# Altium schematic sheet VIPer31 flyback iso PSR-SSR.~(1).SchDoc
size A3; PageSetup: Record=PageOptions¦CenterHorizontal=True¦CenterVertical=True¦PrintScale=0.73¦XCorrection=1.00¦YCorrection=1.00¦PrintKind=1¦BorderSize=5000000¦LeftOffset=0¦BottomOffset=0¦Orientation=2¦PaperLength=1000¦PaperWidth=1000¦Scale=100¦PaperSource=7¦PrintQuality=-3¦MediaType=1¦DitherType=10¦PrintScaleMode=1¦PaperKind=A4¦PaperIndex=9
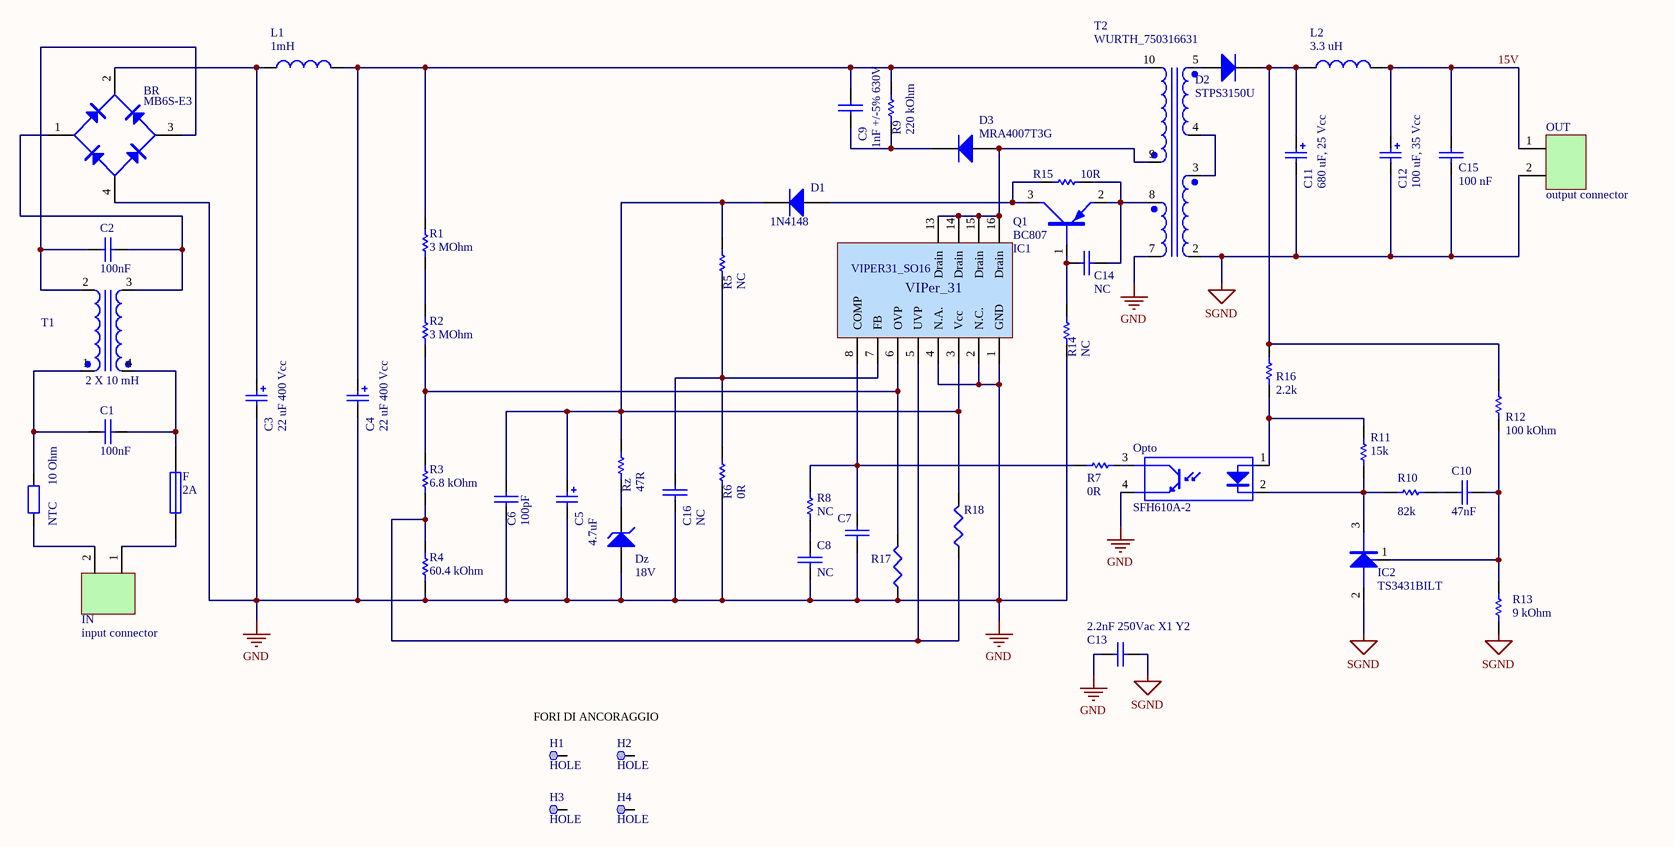
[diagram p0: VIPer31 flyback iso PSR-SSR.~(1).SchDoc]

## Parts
BR  MB6S-E3  [BRIDGE]
C1  100nF  [CAP-13X6]
C2  100nF  [CAP-13X6]
C3  22 uF 400 Vcc  [CAPOL-7.5X16]
C4  22 uF 400 Vcc  [CAPOL-7.5X16]
C5  4.7uF  [R-1206-B2]
C6  100pF  [R-0603-B2]
C7  1 nF 200 Vdc  [R-0603-B2]  (value not drawn)
C8  NC  [R-0603-B2]
C9  1nF +/-5% 630V  [R-1206-B2]
C10  47nF  [R-0603-B2]
C11  680 uF, 25 Vcc  [CAPOL-5X10]
C12  100 uF, 35 Vcc  [CAPOL-2.5X6.3]
C13  2.2nF 250Vac X1 Y2  [MYLAR-10X6]
C14  NC  [R-0603-B2]
C15  100 nF  [R-0603-B2]
C16  NC  [R-0603-B2]
D1  1N4148  [SOD-123]
D2  STPS3150U  [SMB-2]
D3  MRA4007T3G  [SMA-2]
Dz  18V  [SOD-123]
F  2A  [Fuse_3821200041_Wick]
H1  HOLE  [FORO]
H2  HOLE  [FORO]
H3  HOLE  [FORO]
H4  HOLE  [FORO]
IC1  VIPER31_SO16  [SO-16N_2]
IC2  TS3431BILT  [SOT23-3-MIRR]
IN  input connector  [SM.2VITE]
L1  1mH  [CAPOL-5X10]
L2  3.3 uH  [WE_74404043033A_4x4]
NTC  10 Ohm  [B57237S100M-NTC]
Opto  SFH610A-2  [DIP4]
OUT  output connector  [SM.2VITE]
Q1  BC807  [BC817_NEW]
R1  3 MOhm  [R-0805-B2]
R2  3 MOhm  [R-0805-B2]
R3  6.8 kOhm  [R-0805-B2]
R4  60.4 kOhm  [R-0805-B2]
R5  NC  [R-0603-B2]
R6  0R  [R-0603-B2]
R7  0R  [RES-1/4W-3]
R8  NC  [R-0603-B2]
R9  220 kOhm  [R-1206-B2]
R10  82k  [R-0603-B2]
R11  15k  [R-0603-B2]
R12  100 kOhm  [R-0603-B2]
R13  9 kOhm  [R-0603-B2]
R14  NC  [R-0603-B2]
R15  10R  [R-0805-B]
R16  2.2k  [R-0603-B2]
R17  RESISTENZA  [R-0603-B2]  (value not drawn)
R18  RESISTENZA  [R-0603-B2]  (value not drawn)
Rz  47R  [R-0603-B2]
T1  2 X 10 mH  [WE_744821110_Choke]
T2  WURTH_750316631  [WURTH_750316631]

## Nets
GND: BR.4(V-) C3.2 C4.2 C5.2 C6.2 C7.2 C8.2 C13.2 C16.2 Dz.1(A) IC1.1(GND) IC1.2(N.C.) IC1.4(N.A.) Opto.4(E) R4.1 R6.1 R14.1 R17.1 T2.7(OUT)
SGND: C11.2 C12.2 C13.1 C15.2 IC2.2(A) OUT.2 R13.1 T2.2(HV)
15V: C12.1 C15.1 L2.2 OUT.1
NetBR_1: BR.1(AC) C2.2 T1.3(PC)
NetBR_2: BR.2(V+) C3.1 L1.1
NetBR_3: BR.3(AC) C2.1 T1.2(GND)
NetC1_1: C1.1 NTC.2 T1.1(SLS)
NetC1_2: C1.2 F.2 T1.4(LAMP)
NetC4_1: C4.1 C9.1 L1.2 R1.2 R9.2 T2.10(S_GND)
NetC5_1: C5.1 C6.1 D1.2(K) IC1.3(Vcc) R5.2 R18.2 Rz.2
NetC7_1: C7.1 IC1.8(COMP) R7.2 R8.2
NetC8_1: C8.1 R8.1
NetC9_2: C9.2 D3.2(K) R9.1
NetC10_1: C10.1 IC2.1(Ref) R12.1 R13.2
NetC10_2: C10.2 R10.1
NetC11_1: C11.1 D2.2(K) L2.1 R12.2 R16.2
NetC14_1: C14.1 Q1.1(B) R14.2
NetC14_2: C14.2 Q1.2(E) R15.1 T2.8(OUT)
NetC16_1: C16.1 IC1.7(FB) R5.1 R6.2
NetD1_1: D1.1(A) Q1.3(C) R15.2
NetD2_1: D2.1(A) T2.5(P_GND)
NetD3_1: D3.1(A) IC1.13(Drain) IC1.14(Drain) IC1.15(Drain) IC1.16(Drain) T2.9(OUT)
NetDz_2: Dz.2(K) Rz.1
NetF_1: F.1 IN.1
NetIC1_5: IC1.5(UVP) R3.1 R4.2 R18.1
NetIC1_6: IC1.6(OVP) R2.1 R3.2 R17.2
NetIC2_3: IC2.3(K) Opto.2(K) R10.2 R11.1
NetIN_2: IN.2 NTC.1
NetOpto_1: Opto.1(A) R11.2 R16.1
NetOpto_3: Opto.3(C) R7.1
NetR1_1: R1.1 R2.2
NetT2_3: T2.3(DR.) T2.4(VDD)

Not connected (* = marked no-connect by the designer): H1 1; H2 1; H3 1; H4 1

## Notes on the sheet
- FORI DI ANCORAGGIO

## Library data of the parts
BR = BRIDGE1: Diode Bridge
C1 C2 C6 = CAP: 100 pF 250 Vdc multi layer capacitor; Part number: CGA3E3C0G2E101J080AA; Value: 100 pF +/-5%, 250 Vdc
C3 C4 = Cap Pol1: Polarized Capacitor (Radial); Part number: 400BXC68MEFC18X25; Value: 68 uF +/-20%, 400 Vcc, +105°C
C5 = Cap Pol1: Vcc cap 4.7uF 50 Vcc, Kemet; Part number: 35ML10MEFC4X7; Value: 10uF +/-20%, 35 Vcc, +105°C
C7 = CAP: 1 nF 200 Vdc multi layer capacitor; Part number: C0603C102J2GACAUTO; Value: 1 nF +/-5%, 200 Vdc
C8 C14 C16 = CAP
C9 = CAP: 1 nF 630 V multi layer capacitor; Part number: C3216C0G2J102J085AA; Value: 1 nF 630 Vdc
C10 = CAP: 22 nF +/-10%, 100 Vcc, MLCC; Part number: GCM188R72A223KA37D; Value: 22nF, ±10%, 100Vcc
C11 = Cap Pol1: 470 uF +/-20%, 35 Vcc, +105°C; Part number: 25ZLH470MEFC10X12.5
C12 = Cap Pol1: 100 uF +/-20%, 35 Vcc, +105°C; Part number: 35ZLH100MEFC6.3X11
C13 = CAP: 2.2 nF 2000 V single layer capacitor; Part number: DE2E3KY222MA2BM01F
C15 = CAP: 100nF ±10%, 25 Vcc, MLCC; Part number: C0603C104K3RACTU
D1 = Diode: small signal diode; Part number: STPS1150A; Value: 1 A, 150 V
D2 = Diode: Schottky diode, 10A, 200 V; Part number: STPS2200UF
D3 = Diode: Silicon Diode, 1 A, 1000 V
Dz = D Zener: Zener Diode; Part number: MMSZ5248B-V-GS08; Value: 18W, 500 mW
F = Fuse 1: Fuse 2A,  250 Vca; Part number: 3403.0169.24
IC1 = VIPER31_SO16: Integrato
IC2 = TS432: 1.24 V VREF SHUNT; Part number: TS432ILT
IN OUT = M.2VITE: Morsetti
L1 L2 = Inductor: FIXED IND 3.3UH 3.23A 33 MOHM; Part number: 74404043033A
NTC = Res2: Part number: NTPA7100LBMB0
Opto = OPTO_1: Opto ingresso 60 Vdc
Q1 = PNP_BC807: PNP Transitstor 0.5A, 45 V, hfe 30; Part number: BC807-40LT3G
R1 R2 = Res1: 3 MOhm +/-1%  0.125W, 0805 Vishay; Part number: ERJP08J105V; Value: 1MOhm +/-5%
R3 = Res1: 6.8 kOhm +/-1% 0.125W, 0805 Panasonic; Part number: ERJP08J105V; Value: 1MOhm +/-5%
R4 = Res1: 60.4 kOhm +/-1% 0.125W, 0805 Panasonic; Part number: ERJP08J105V; Value: 1MOhm +/-5%
R5 R8 R14 = Res1: Not connected
R6 R7 = Res1: 0Ω, 0.25W, pkg 0603, serie CRCW; Part number: CRCW06030000Z0EAHP; Value: 0 Ohm, 0.25W
R9 = Res1: 220 KOhm +/-5%, 0.33W, 1206, serie ERJT08; Part number: ERJT08J224V
R10 = Res1: 470kΩ ±1%, 0.1W; Part number: CRCW0603470KFKEA
R11 = Res1: 22KΩ ±1%, 0.1W; Part number: CRCW060322K0FKEA
R12 = Res1: Not connected; Part number: CRCW0603130KFKEA; Value: 130 kΩ ±1%, 0.1 W
R13 = Res1: 15 kΩ ±1%, 0.1W, 0603; Part number: CRG0603F15K
R15 = Res1: 10Ω, 0.1W, pkg 0603, serie CRG0603; Part number: CRG0603F10R; Value: 10 Ohm, 0.1W
R16 = Res1: 470Ω ±1%, 0.1W; Part number: CRCW0603470RFKEA
R17 R18 = RESISTENZA: Resistor
Rz = Res1: 47Ω ±1%, 0.125W; Part number: CRG0805F47R
T1 = CM CHOKE: Common Mode Choke, Lo=10 mH, Rdc=350 mOhm, Idc=0.7A, Un=230 Vac; Part number: 744821110
T2 = TRANSFORMER_WURTH_750316631: Center-tapped transformer; Value: LP 1.5 mH, out1 12V, out2 6V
